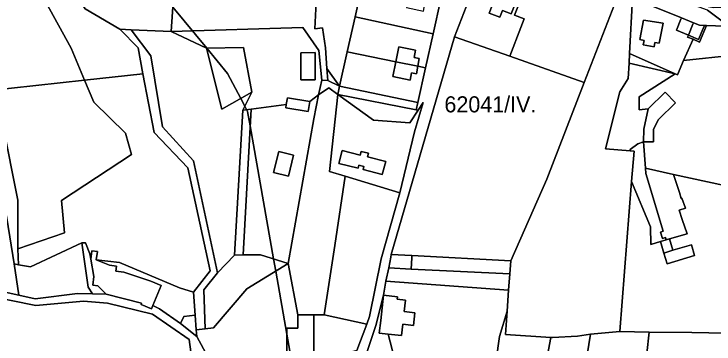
# Model space of a CAD drawing. Extents: x -502026 to -497664, y -1143484 to -1138019.
# Drawn here: x -499088.9 to -498740.2, y -1141619.2 to -1141455 of the extents above; entities that cross this region are included whole.
import ezdxf

# ---------------------------------------------------------------- set-up
doc = ezdxf.new("R2010")
doc.units = 0
for name, color, linetype in [('25', 7, 'Continuous'), ('31', 7, 'Continuous'), ('37', 7, 'Continuous'), ('43', 7, 'Continuous'), ('55', 7, 'Continuous'), ('62', 7, 'Continuous'), ('7', 7, 'Continuous')]:
    doc.layers.add(name, color=color, linetype=linetype)

msp = doc.modelspace()

# ---------------------------------------------------------------- linework, layer by layer
at = {"layer": '25'}
for points in [[(-498839.96, -1141423.17), (-498834.17, -1141425.47), (-498787.53, -1141444.07), (-498804.84, -1141488.98), (-498841.9, -1141476), (-498836.37, -1141461.72), (-498834.71, -1141457.43), (-498839.54, -1141455.56), (-498836.03, -1141446.78), (-498841.68, -1141444.52), (-498841.17, -1141443.12), (-498844.65, -1141441.82), (-498845.14, -1141443.14), (-498852.72, -1141440.11), (-498856.29, -1141449.05), (-498861.93, -1141446.88), (-498850.3, -1141419.16)], [(-498973.38, -1141431.94), (-498955.42, -1141440.85), (-498941.25, -1141442.26), (-498937.95, -1141442.23), (-498939.09, -1141462.4), (-498935.24, -1141461.91), (-498933.78, -1141471.82), (-498933.01, -1141482.12), (-498932.56, -1141488.07), (-498935.53, -1141487.84), (-498937.05, -1141473.15), (-498944.94, -1141461.61), (-499010.52, -1141463.61), (-499009.25, -1141443.98), (-499000, -1141425.24), (-498990.91, -1141426.4), (-498975.98, -1141430.65)], [(-498891.91, -1141444.36), (-498893.41, -1141451.77), (-498884.83, -1141453.52), (-498884.17, -1141449.85), (-498881.78, -1141450.34), (-498881.01, -1141446.54), (-498876.29, -1141447.41), (-498880.08, -1141464.76), (-498918.99, -1141456.4), (-498915.13, -1141439.04)], [(-498784.3, -1141445.42), (-498780.88, -1141446.84), (-498782.26, -1141474.61), (-498782.49, -1141479.36), (-498782.95, -1141487.08), (-498787.17, -1141493.68), (-498794.34, -1141521.98), (-498781.98, -1141523.08), (-498780.05, -1141523.25), (-498781.24, -1141538.26), (-498787.15, -1141613), (-498801.68, -1141614.26), (-498808.23, -1141615.35), (-498820.61, -1141616.01), (-498821.5, -1141615.93), (-498844.02, -1141614.47), (-498843.3, -1141602.91), (-498842.64, -1141592.44), (-498841.92, -1141584.26), (-498841.36, -1141577.83), (-498823.46, -1141537.22), (-498804.84, -1141488.98), (-498787.53, -1141444.07)], [(-498756.41, -1141456.87), (-498756.71, -1141457.6), (-498758.96, -1141463), (-498752.97, -1141465.49), (-498753.36, -1141466.42), (-498750.65, -1141467.55), (-498755.37, -1141478.17), (-498758.49, -1141485.19), (-498759.62, -1141484.68), (-498782.26, -1141474.61), (-498780.88, -1141446.84)], [(-498880.08, -1141464.76), (-498883.92, -1141481.68), (-498887.73, -1141480.93), (-498887.01, -1141477.1), (-498889.5, -1141476.63), (-498888.81, -1141472.97), (-498897.26, -1141471.29), (-498898.74, -1141478.69), (-498922.85, -1141473.72), (-498918.99, -1141456.4)], [(-498765.59, -1141459.59), (-498775.41, -1141457.96), (-498777.1, -1141467.72), (-498775.08, -1141468.07), (-498775.53, -1141470.23), (-498770.09, -1141471.36), (-498769.68, -1141469.16), (-498767.61, -1141469.54)], [(-498730.32, -1141461.17), (-498730.31, -1141475.48), (-498755.37, -1141478.17), (-498750.65, -1141467.55), (-498747.41, -1141468.9), (-498743.97, -1141460.64)], [(-498743.97, -1141460.64), (-498747.41, -1141468.9), (-498750.65, -1141467.55), (-498753.36, -1141466.42), (-498752.97, -1141465.49), (-498747.95, -1141467.59), (-498745.7, -1141462.19), (-498745.03, -1141460.6)], [(-498841.9, -1141476), (-498804.84, -1141488.98), (-498823.46, -1141537.22), (-498841.36, -1141577.83), (-498890.75, -1141575.21), (-498900.97, -1141574.67), (-498869.5, -1141466.33)], [(-498898.74, -1141478.69), (-498900.21, -1141486.1), (-498891.61, -1141487.92), (-498890.93, -1141484.29), (-498888.45, -1141484.76), (-498887.73, -1141480.93), (-498883.92, -1141481.68), (-498887.77, -1141498.98), (-498926.68, -1141490.93), (-498922.85, -1141473.72)], [(-498759.62, -1141484.68), (-498782.49, -1141479.36), (-498782.26, -1141474.61)], [(-498730.2, -1141482.67), (-498731.44, -1141484.27), (-498728.37, -1141513.04), (-498730.54, -1141529.13), (-498734.96, -1141540.38), (-498760.47, -1141534.79), (-498774.41, -1141531.73), (-498775.27, -1141518.59), (-498770.38, -1141518.64), (-498770.32, -1141512.29), (-498767.95, -1141507.51), (-498759.4, -1141499.21), (-498764.51, -1141493.88), (-498773.09, -1141502.21), (-498777.46, -1141502.69), (-498777.56, -1141496.1), (-498759.62, -1141484.68), (-498758.49, -1141485.19), (-498755.37, -1141478.17), (-498730.31, -1141475.48)], [(-498759.62, -1141484.68), (-498777.56, -1141496.1), (-498777.46, -1141502.69), (-498773.09, -1141502.21), (-498775.21, -1141512.24), (-498775.27, -1141518.59), (-498778.12, -1141519.6), (-498781.93, -1141522.36), (-498781.98, -1141523.08), (-498794.34, -1141521.98), (-498787.17, -1141493.68), (-498782.95, -1141487.08), (-498782.49, -1141479.36)], [(-498887.77, -1141498.98), (-498888.59, -1141502.67), (-498927.62, -1141494.98), (-498926.68, -1141490.93)], [(-498952.32, -1141579.09), (-498966.03, -1141574.81), (-498974.66, -1141574.86), (-498970.79, -1141502.25), (-498953.23, -1141499.96), (-498953.5, -1141501.64), (-498942.34, -1141503.42), (-498941.55, -1141498.48), (-498937.15, -1141495.11), (-498939.6, -1141507.07)], [(-498949.64, -1141525.21), (-498957.01, -1141523.44), (-498959.53, -1141533.84), (-498952.14, -1141535.58)], [(-498841.36, -1141577.83), (-498841.92, -1141584.26), (-498891.04, -1141581.86), (-498890.8, -1141576.36), (-498890.75, -1141575.21)], [(-498947.46, -1141604.71), (-498947.46, -1141611.24), (-498952.98, -1141611.24), (-498952.98, -1141629.37), (-498947.46, -1141629.37), (-498981.99, -1141637.66), (-498988.93, -1141631.68), (-498997.73, -1141615.43), (-498998.08, -1141612.11), (-498993.7, -1141611.61), (-498989.42, -1141611.16), (-498972.97, -1141591.73), (-498952.32, -1141579.09)], [(-498891.04, -1141581.86), (-498841.92, -1141584.26), (-498842.64, -1141592.44), (-498903.64, -1141587.99), (-498902.14, -1141581.32)], [(-498902.53, -1141614.3), (-498899.43, -1141626.42), (-498913.62, -1141624.92), (-498908.71, -1141609.93), (-498904.82, -1141594.87), (-498906.21, -1141607.46), (-498906.91, -1141613.82)], [(-498913.2, -1141609.38), (-498918.04, -1141622.38), (-498939.49, -1141627.48), (-498939.49, -1141611.24), (-498939.49, -1141604.71), (-498934.35, -1141604.71)], [(-498821.5, -1141615.93), (-498820.61, -1141616.01), (-498808.23, -1141615.35), (-498801.68, -1141614.26), (-498812.29, -1141680.22), (-498832.5, -1141673.92)]]:
    msp.add_lwpolyline(points, close=True, dxfattribs=at)
at = {"layer": '31'}
for points in [[(-498935.53, -1141487.84), (-498937.15, -1141495.11), (-498941.55, -1141498.48), (-498952.71, -1141496.7), (-498953.23, -1141499.96), (-498970.79, -1141502.25), (-498974.91, -1141502.79), (-498970.47, -1141493.9), (-498974.48, -1141471.68), (-498992.9, -1141472.01), (-499010.52, -1141463.61), (-498944.94, -1141461.61), (-498937.05, -1141473.15)], [(-498938.87, -1141487.72), (-498938.93, -1141474.17), (-498946.06, -1141474.2), (-498946, -1141487.75)], [(-498999.46, -1141593.37), (-499006.48, -1141591.21), (-499036.32, -1141578.54), (-499047.87, -1141577.31), (-499047.3, -1141573.23), (-499050.02, -1141572.85), (-499050.59, -1141576.93), (-499051.06, -1141574.27), (-499053.17, -1141568.91), (-499055.03, -1141568.91), (-499080.57, -1141580.7), (-499086.53, -1141579.72), (-499086.96, -1141571.81), (-499063.74, -1141563.83), (-499065.13, -1141547.8), (-499030.26, -1141524.85), (-499033.4, -1141514.28), (-499049.08, -1141498.83), (-499053.7, -1141487.88), (-499024.61, -1141484.68), (-499019.12, -1141513.97), (-499002.28, -1141531.57), (-498991.12, -1141582.75)], [(-498842.64, -1141592.44), (-498843.3, -1141602.91), (-498846.98, -1141615.47), (-498855.78, -1141677.89), (-498858.25, -1141677.23), (-498884.08, -1141657.97), (-498885.93, -1141656.59), (-498892.15, -1141653.1), (-498893.08, -1141652.59), (-498895.55, -1141641.78), (-498864.48, -1141649.48), (-498862.04, -1141630.36), (-498899.43, -1141626.42), (-498902.53, -1141614.3), (-498895.86, -1141615.03), (-498895.23, -1141609.38), (-498889.94, -1141609.97), (-498889.24, -1141603.61), (-498894.53, -1141603.03), (-498893.91, -1141597.36), (-498897.99, -1141596.91), (-498897.85, -1141595.64), (-498904.82, -1141594.87), (-498903.64, -1141587.99)], [(-498821.5, -1141615.93), (-498832.5, -1141673.92), (-498812.29, -1141680.22), (-498801.68, -1141614.26), (-498787.15, -1141613), (-498772.57, -1141613.25), (-498773.73, -1141623.84), (-498767.62, -1141628.33), (-498775.76, -1141662.06), (-498776.89, -1141671.76), (-498808.21, -1141663.92), (-498812.44, -1141689.43), (-498855.78, -1141677.89), (-498846.98, -1141615.47), (-498843.3, -1141602.91), (-498844.02, -1141614.47)]]:
    msp.add_lwpolyline(points, close=True, dxfattribs=at)
msp.add_lwpolyline([(-498717.42, -1141614.15), (-498751.28, -1141613.52), (-498772.57, -1141613.25), (-498787.15, -1141613), (-498781.24, -1141538.26), (-498771.88, -1141560.95), (-498771.66, -1141569.66), (-498766.86, -1141568.23), (-498765.17, -1141573.9), (-498763.55, -1141579.31), (-498749.87, -1141575.22), (-498751.49, -1141569.81), (-498760.69, -1141572.56), (-498762.38, -1141566.9), (-498753.65, -1141564.31), (-498756.01, -1141557.25), (-498757.54, -1141552.65), (-498754.48, -1141551.57), (-498756.22, -1141546.65), (-498756.51, -1141546.74), (-498757.47, -1141543.85), (-498760.47, -1141534.79), (-498734.96, -1141540.38)], dxfattribs=at)
at = {"layer": '37'}
for points in [[(-498903.17, -1141379.63), (-498910.04, -1141415.41), (-498872.97, -1141422.84), (-498873.88, -1141429.08), (-498911.27, -1141421.81), (-498912.02, -1141425.09), (-498915.13, -1141439.04), (-498918.99, -1141456.4), (-498922.85, -1141473.72), (-498926.68, -1141490.93), (-498933.01, -1141482.12), (-498933.78, -1141471.82), (-498935.24, -1141461.91), (-498939.09, -1141462.4), (-498937.95, -1141442.23), (-498940.59, -1141378.11)], [(-499053.7, -1141487.88), (-499102.4, -1141493.22), (-499113.08, -1141471.53), (-499111.22, -1141460.38), (-499117.03, -1141448.3), (-499108.88, -1141432.13), (-499091.92, -1141414.58), (-499060.45, -1141471.88)], [(-499010.52, -1141463.61), (-498992.9, -1141472.01), (-498985.42, -1141502.25), (-498970.47, -1141493.9), (-498974.91, -1141502.79), (-498979.04, -1141574.89), (-498987.48, -1141583.77), (-498999.51, -1141528.07), (-499014.89, -1141511.05), (-499020.74, -1141475.82), (-499030.54, -1141462.79)], [(-499088.85, -1141579.34), (-499086.47, -1141594.92), (-499115.1, -1141588.54), (-499131.4, -1141589.23), (-499152.88, -1141587.86), (-499149.04, -1141576.7), (-499126.95, -1141553.67), (-499120.33, -1141549.34), (-499129.56, -1141482.67), (-499127.76, -1141470.88), (-499120.4, -1141466.57), (-499104.25, -1141501.27), (-499092.34, -1141556.64)], [(-498970.47, -1141493.9), (-498985.42, -1141502.25), (-498992.9, -1141472.01), (-498974.48, -1141471.68)], [(-498926.68, -1141490.93), (-498932.56, -1141488.07), (-498933.01, -1141482.12)], [(-499086.96, -1141571.81), (-499086.96, -1141547.65), (-499094.5, -1141509.29), (-499102.4, -1141493.22), (-499053.7, -1141487.88), (-499049.08, -1141498.83), (-499033.4, -1141514.28), (-499030.26, -1141524.85), (-499065.13, -1141547.8), (-499063.74, -1141563.83)], [(-498932.56, -1141488.07), (-498926.68, -1141490.93), (-498927.62, -1141494.98), (-498932.07, -1141491.63), (-498937.15, -1141495.11), (-498935.53, -1141487.84)], [(-498927.62, -1141494.98), (-498931.77, -1141533.33), (-498923.89, -1141535.71), (-498929.14, -1141570.16), (-498934.35, -1141604.71), (-498939.49, -1141604.71), (-498947.46, -1141604.71), (-498952.32, -1141579.09), (-498939.6, -1141507.07), (-498937.15, -1141495.11), (-498932.07, -1141491.63)], [(-498887.59, -1141502.87), (-498885.01, -1141499), (-498889.34, -1141513.58), (-498896.76, -1141543.88), (-498923.89, -1141535.71), (-498931.77, -1141533.33), (-498927.62, -1141494.98), (-498909.86, -1141507.87), (-498891.74, -1141509.07)], [(-498974.66, -1141574.86), (-498979.04, -1141574.89), (-498974.91, -1141502.79), (-498970.79, -1141502.25)], [(-498925.36, -1141522.84), (-498927.01, -1141529.29), (-498917.47, -1141531.74), (-498917.08, -1141530.24), (-498914.64, -1141530.87), (-498915.02, -1141532.38), (-498905.47, -1141534.82), (-498903.75, -1141528.4), (-498912.81, -1141526.05), (-498912.35, -1141524.25), (-498915.9, -1141523.34), (-498916.37, -1141525.15)], [(-498896.76, -1141543.88), (-498906.01, -1141576.76), (-498911.81, -1141605.52), (-498913.2, -1141609.38), (-498934.35, -1141604.71), (-498929.14, -1141570.16), (-498923.89, -1141535.71)], [(-499049.69, -1141594.21), (-499057.15, -1141594.05), (-499078.38, -1141596.71), (-499086.47, -1141594.92), (-499088.85, -1141579.34), (-499086.53, -1141579.72), (-499080.57, -1141580.7), (-499055.03, -1141568.91), (-499051.94, -1141590.96)], [(-498952.32, -1141579.09), (-498972.97, -1141591.73), (-498989.42, -1141611.16), (-498993.7, -1141611.61), (-498994.37, -1141592.21), (-498987.48, -1141583.77), (-498979.04, -1141574.89), (-498974.66, -1141574.86), (-498966.03, -1141574.81)], [(-498997.4, -1141647.48), (-499015.11, -1141653.67), (-499036.81, -1141671.03), (-499119.22, -1141664.12), (-499130.29, -1141632.61), (-499135.02, -1141600.22), (-499134.62, -1141592.19), (-499113.37, -1141592.87), (-499078.04, -1141599.95), (-499054.3, -1141597.84), (-499042.32, -1141598.82), (-499019.94, -1141604.31), (-499001.68, -1141617)]]:
    msp.add_lwpolyline(points, close=True, dxfattribs=at)
for points in [[(-499100.43, -1141399.49), (-499078.93, -1141413.23), (-499053.49, -1141452.34), (-499036.07, -1141462.56), (-499027.01, -1141471.86), (-499024.61, -1141484.68), (-499053.7, -1141487.88), (-499060.45, -1141471.88), (-499091.92, -1141414.58)], [(-499094.5, -1141509.29), (-499086.96, -1141547.65), (-499086.96, -1141571.81), (-499086.53, -1141579.72), (-499088.85, -1141579.34), (-499092.34, -1141556.64)]]:
    msp.add_lwpolyline(points, dxfattribs=at)
at = {"layer": '43'}
for points in [[(-499030.54, -1141462.79), (-499020.74, -1141475.82), (-499014.89, -1141511.05), (-498999.51, -1141528.07), (-498987.48, -1141583.77), (-498994.37, -1141592.21), (-498993.7, -1141611.61), (-498998.08, -1141612.11), (-498998.56, -1141604.82), (-498999.46, -1141593.37), (-498991.12, -1141582.75), (-499002.28, -1141531.57), (-499019.12, -1141513.97), (-499024.61, -1141484.68), (-499027.01, -1141471.86), (-499036.07, -1141462.56)], [(-498717.42, -1141614.15), (-498698.67, -1141667.49), (-498695.49, -1141677.7), (-498709.13, -1141683.37), (-498719.96, -1141686.46), (-498736.92, -1141687.62), (-498754.9, -1141684.48), (-498778.26, -1141684.08), (-498776.89, -1141671.76), (-498775.76, -1141662.06), (-498767.62, -1141628.33), (-498773.73, -1141623.84), (-498772.57, -1141613.25), (-498751.28, -1141613.52)]]:
    msp.add_lwpolyline(points, close=True, dxfattribs=at)
at = {"layer": '55'}
for points in [[(-499019.87, -1141429.37), (-499011.32, -1141427.42), (-499000.9, -1141423.25), (-499000, -1141425.24), (-499009.25, -1141443.98), (-499010.52, -1141463.61), (-499030.54, -1141462.79), (-499036.07, -1141462.56), (-499053.49, -1141452.34), (-499078.93, -1141413.23), (-499066.58, -1141408.37), (-499064.36, -1141412.4), (-499056.46, -1141407.4), (-499047.27, -1141426.59), (-499033.7, -1141432.29)], [(-498845.14, -1141443.14), (-498845.38, -1141443.77), (-498845.74, -1141444.72), (-498848.13, -1141443.8), (-498852.27, -1141454.5), (-498846.84, -1141456.58), (-498845.56, -1141453.22), (-498841.26, -1141454.89), (-498838.42, -1141447.56), (-498842.26, -1141446.08), (-498841.9, -1141445.11), (-498841.68, -1141444.52), (-498836.03, -1141446.78), (-498839.54, -1141455.56), (-498834.71, -1141457.43), (-498836.37, -1141461.72), (-498841.9, -1141476), (-498869.5, -1141466.33), (-498863.67, -1141451.35), (-498861.93, -1141446.88), (-498856.29, -1141449.05), (-498852.72, -1141440.11)], [(-498769.13, -1141441.85), (-498760.33, -1141448.11), (-498740.54, -1141451.68), (-498719.01, -1141451.31), (-498700.45, -1141450.92), (-498696.28, -1141450.83), (-498694.16, -1141450.78), (-498614.4, -1141465.78), (-498586.55, -1141499.57), (-498589.12, -1141510.6), (-498595.94, -1141502.21), (-498619.69, -1141473.1), (-498694.46, -1141459.99), (-498705.72, -1141460.68), (-498722.2, -1141461.68), (-498730.32, -1141461.17), (-498743.97, -1141460.64), (-498745.03, -1141460.6), (-498747.52, -1141460.52), (-498750.42, -1141459.33), (-498756.41, -1141456.87), (-498780.88, -1141446.84), (-498784.3, -1141445.42), (-498785.36, -1141439.68)], [(-498841.68, -1141444.52), (-498841.9, -1141445.11), (-498842.26, -1141446.08), (-498838.42, -1141447.56), (-498841.26, -1141454.89), (-498845.56, -1141453.22), (-498846.84, -1141456.58), (-498852.27, -1141454.5), (-498848.13, -1141443.8), (-498845.74, -1141444.72), (-498845.38, -1141443.77), (-498845.14, -1141443.14), (-498844.65, -1141441.82), (-498841.17, -1141443.12)], [(-498765.59, -1141459.59), (-498767.61, -1141469.54), (-498769.68, -1141469.16), (-498770.09, -1141471.36), (-498775.53, -1141470.23), (-498775.08, -1141468.07), (-498777.1, -1141467.72), (-498775.41, -1141457.96)], [(-498750.42, -1141459.33), (-498750.73, -1141460.09), (-498752.97, -1141465.49), (-498758.96, -1141463), (-498756.71, -1141457.6), (-498756.41, -1141456.87)], [(-498745.03, -1141460.6), (-498745.7, -1141462.19), (-498747.95, -1141467.59), (-498752.97, -1141465.49), (-498750.73, -1141460.09), (-498750.42, -1141459.33), (-498747.52, -1141460.52)], [(-498887.73, -1141480.93), (-498898.74, -1141478.69), (-498897.26, -1141471.29), (-498888.81, -1141472.97), (-498889.5, -1141476.63), (-498887.01, -1141477.1)], [(-498938.87, -1141487.72), (-498946, -1141487.75), (-498946.06, -1141474.2), (-498938.93, -1141474.17)], [(-498887.73, -1141480.93), (-498888.45, -1141484.76), (-498890.93, -1141484.29), (-498891.61, -1141487.92), (-498900.21, -1141486.1), (-498898.74, -1141478.69)], [(-498888.59, -1141502.67), (-498887.59, -1141502.87), (-498891.74, -1141509.07), (-498909.86, -1141507.87), (-498927.62, -1141494.98)], [(-498775.27, -1141518.59), (-498775.21, -1141512.24), (-498773.09, -1141502.21), (-498764.51, -1141493.88), (-498759.4, -1141499.21), (-498767.95, -1141507.51), (-498770.32, -1141512.29), (-498770.38, -1141518.64)], [(-498941.55, -1141498.48), (-498942.34, -1141503.42), (-498953.5, -1141501.64), (-498953.23, -1141499.96), (-498952.71, -1141496.7)], [(-498774.41, -1141531.73), (-498774.18, -1141534.26), (-498765.54, -1141563.01), (-498766.95, -1141563.5), (-498765.86, -1141566.68), (-498764.43, -1141566.19), (-498764.07, -1141567.4), (-498766.86, -1141568.23), (-498771.66, -1141569.66), (-498771.88, -1141560.95), (-498781.24, -1141538.26), (-498780.05, -1141523.25), (-498781.98, -1141523.08), (-498781.93, -1141522.36), (-498778.12, -1141519.6), (-498775.27, -1141518.59)], [(-498949.64, -1141525.21), (-498952.14, -1141535.58), (-498959.53, -1141533.84), (-498957.01, -1141523.44)], [(-498925.36, -1141522.84), (-498916.37, -1141525.15), (-498915.9, -1141523.34), (-498912.35, -1141524.25), (-498912.81, -1141526.05), (-498903.75, -1141528.4), (-498905.47, -1141534.82), (-498915.02, -1141532.38), (-498914.64, -1141530.87), (-498917.08, -1141530.24), (-498917.47, -1141531.74), (-498927.01, -1141529.29)], [(-498760.47, -1141534.79), (-498757.47, -1141543.85), (-498756.51, -1141546.74), (-498756.22, -1141546.65), (-498754.48, -1141551.57), (-498757.54, -1141552.65), (-498756.01, -1141557.25), (-498753.65, -1141564.31), (-498762.38, -1141566.9), (-498764.07, -1141567.4), (-498764.43, -1141566.19), (-498765.86, -1141566.68), (-498766.95, -1141563.5), (-498765.54, -1141563.01), (-498774.18, -1141534.26), (-498774.41, -1141531.73)], [(-499050.59, -1141576.93), (-499049.05, -1141585.65), (-499049.57, -1141589.9), (-499047.03, -1141590.21), (-499042.9, -1141594.35), (-499049.69, -1141594.21), (-499051.94, -1141590.96), (-499055.03, -1141568.91), (-499053.17, -1141568.91), (-499051.06, -1141574.27)], [(-498760.69, -1141572.56), (-498765.17, -1141573.9), (-498766.86, -1141568.23), (-498764.07, -1141567.4), (-498762.38, -1141566.9)], [(-499047.87, -1141577.31), (-499041.29, -1141580.01), (-499037.8, -1141580.43), (-499038.11, -1141582.92), (-499034.13, -1141583.41), (-499020.68, -1141587.86), (-499015.52, -1141590.03), (-499019.7, -1141599.96), (-499020.41, -1141601.64), (-499025.57, -1141599.47), (-499025.32, -1141598.87), (-499042.9, -1141594.35), (-499047.03, -1141590.21), (-499049.57, -1141589.9), (-499049.05, -1141585.65), (-499050.59, -1141576.93), (-499050.02, -1141572.85), (-499047.3, -1141573.23)], [(-498765.17, -1141573.9), (-498760.69, -1141572.56), (-498751.49, -1141569.81), (-498749.87, -1141575.22), (-498763.55, -1141579.31)], [(-498890.75, -1141575.21), (-498890.8, -1141576.36), (-498891.04, -1141581.86), (-498902.14, -1141581.32), (-498901.19, -1141575.92), (-498900.97, -1141574.67)], [(-498902.53, -1141614.3), (-498906.91, -1141613.82), (-498906.21, -1141607.46), (-498904.82, -1141594.87), (-498897.85, -1141595.64), (-498897.99, -1141596.91), (-498893.91, -1141597.36), (-498894.53, -1141603.03), (-498889.24, -1141603.61), (-498889.94, -1141609.97), (-498895.23, -1141609.38), (-498895.86, -1141615.03)], [(-498939.49, -1141627.48), (-498947.46, -1141629.37), (-498952.98, -1141629.37), (-498952.98, -1141611.24), (-498947.46, -1141611.24), (-498947.46, -1141604.71), (-498939.49, -1141604.71), (-498939.49, -1141611.24)]]:
    msp.add_lwpolyline(points, close=True, dxfattribs=at)
for points in [[(-498918.04, -1141622.38), (-498913.2, -1141609.38), (-498911.81, -1141605.52), (-498906.01, -1141576.76), (-498896.76, -1141543.88), (-498889.34, -1141513.58), (-498885.01, -1141499), (-498887.59, -1141502.87), (-498888.59, -1141502.67), (-498887.77, -1141498.98), (-498883.92, -1141481.68), (-498880.08, -1141464.76), (-498876.29, -1141447.41)], [(-498863.67, -1141451.35), (-498869.5, -1141466.33), (-498900.97, -1141574.67), (-498901.19, -1141575.92), (-498902.14, -1141581.32), (-498903.64, -1141587.99), (-498904.82, -1141594.87), (-498908.71, -1141609.93), (-498913.62, -1141624.92)], [(-499115.1, -1141588.54), (-499086.47, -1141594.92), (-499078.38, -1141596.71), (-499057.15, -1141594.05), (-499049.69, -1141594.21), (-499042.9, -1141594.35), (-499025.32, -1141598.87), (-499025.57, -1141599.47), (-499020.41, -1141601.64), (-499019.7, -1141599.96), (-499016.32, -1141601.63), (-499006, -1141609.03), (-498997.73, -1141615.43), (-498988.93, -1141631.68)], [(-498997.4, -1141647.48), (-499001.68, -1141617), (-499019.94, -1141604.31), (-499042.32, -1141598.82), (-499054.3, -1141597.84), (-499078.04, -1141599.95), (-499113.37, -1141592.87)]]:
    msp.add_lwpolyline(points, dxfattribs=at)
at = {"layer": '62'}
for points in [[(-498732.88, -1141461.07), (-498743.5, -1141453), (-498754.13, -1141449.23), (-498759, -1141447.5), (-498768.8, -1141442.08), (-498769.25, -1141441.83), (-498769.97, -1141441.44), (-498797, -1141426.5), (-498826, -1141408.5), (-498824.59, -1141404.99), (-498824.2, -1141404.03), (-498808.5, -1141365), (-498764.5, -1141268), (-498753, -1141249), (-498751.13, -1141249.15), (-498740.5, -1141250), (-498701.9, -1141248.44)], [(-499099.42, -1141303.13), (-499074.21, -1141304.14), (-499072.84, -1141304.08), (-499073, -1141305), (-499074.13, -1141311.93), (-499077.5, -1141332.5), (-499076.24, -1141351.46), (-499075.5, -1141362.5), (-499073.72, -1141365.41), (-499052.5, -1141400), (-499026.93, -1141430.86), (-499009.74, -1141451.61), (-498992.85, -1141472.01), (-498982.5, -1141484.5), (-498975.94, -1141496.96), (-498973.92, -1141500.8), (-498973.01, -1141502.54), (-498972.5, -1141503.5), (-498971.24, -1141510.66), (-498959.58, -1141576.82), (-498958.51, -1141582.88), (-498952.98, -1141614.25), (-498950.32, -1141629.37)], [(-498950.32, -1141629.37), (-498952.98, -1141614.25), (-498958.51, -1141582.88), (-498959.58, -1141576.82), (-498971.24, -1141510.66), (-498972.5, -1141503.5), (-498973.01, -1141502.54), (-498973.92, -1141500.8), (-498975.94, -1141496.96), (-498982.5, -1141484.5), (-498992.85, -1141472.01), (-499009.74, -1141451.61)], [(-498743.5, -1141453), (-498732.88, -1141461.07)]]:
    msp.add_lwpolyline(points, dxfattribs=at)
at = {"layer": '7'}
for points in [[(-498999.46, -1141593.37), (-498998.56, -1141604.82), (-499004.3, -1141605.48), (-499006, -1141609.03), (-499016.32, -1141601.63), (-499019.7, -1141599.96), (-499015.52, -1141590.03), (-499020.68, -1141587.86), (-499034.13, -1141583.41), (-499038.11, -1141582.92), (-499037.8, -1141580.43), (-499041.29, -1141580.01), (-499047.87, -1141577.31), (-499036.32, -1141578.54), (-499006.48, -1141591.21)], [(-498998.08, -1141612.11), (-498997.73, -1141615.43), (-499006, -1141609.03), (-499004.3, -1141605.48), (-498998.56, -1141604.82)]]:
    msp.add_lwpolyline(points, close=True, dxfattribs=at)

# ---------------------------------------------------------------- texts
at = {"layer": '62'}
msp.add_text('62041/IV.', height=8, dxfattribs=at).set_placement((-498874.48, -1141503.91))

doc.saveas('drawing.dxf')
